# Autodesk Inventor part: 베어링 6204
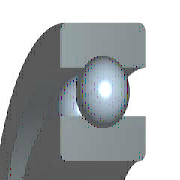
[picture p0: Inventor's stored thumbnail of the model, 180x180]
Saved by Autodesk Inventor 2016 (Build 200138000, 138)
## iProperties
IsCustomPart: 0
Created: 2018-09
Part Number: 베어링 6204
Material: 스테인리스강
Description: 깊은 그루브 볼 베어링
Document SubType Name: Modeling
Standard: KS B 2023
Standards Organization: KS
Language: ko-KR
Size Designation: 6204 - 20 x 47 x 14
Categories: <MemberInstance><Categories><Category DisplayName="샤프트 부품" InternalName="7f7aeb1f-a693-4053-b835-cee3144e0d98" Mnemonic="SHFT"><Category DisplayName="베어링" Inter
Density: 8.08 g/cm^3
Mass: 107.173 g
Surface Area: 87.8912 cm^2
Volume: 13.264 cm^3
Appearance: 노란색
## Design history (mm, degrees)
sketch "스케치" dims "d0" = 7.02 (= -0.26 x WD + 0.26 x BD)
  geometry: L1 (3.49, 16.75)-(10.51, 16.75); L2 (7, 16.75)-(7, 13.24); L3 (7, 16.75)-(7, 20.26); L4 (4.392, 14.401)-(0, 14.401); L5 (0, 10)-(14, 10); L6 (4.392, 19.099)-(0, 19.099); L7 (0, 23.5)-(14, 23.5); L8 (14, 10)-(14, 14.401); L9 (9.608, 14.401)-(14, 14.401); L10 (9.608, 19.099)-(14, 19.099); L11 (14, 23.5)-(14, 19.099); L12 (-1.4, 0)-(8.4, 0) reference; L13 (0, -0.3)-(0, 5.3) reference
  constraints: 22 end point, 4 point on line, 2 collinear, 2 perpendicular, 2 symmetric about line, 1 midpoint, 1 parallel, 14 other
  dimensions: "d9" = 20 diameter of L5 L12 (= WD); "d11" = 47 diameter of L7 L12 (= BD); "d12" = 14 distance between parallel lines of L8 L13 (= KB); "d13" = 28.802 diameter of L9 L12 (= 0.326 x BD + 0.674 x WD)
revolve "본체" stored, may be unused: angle "d6" = 90 deg
revolve "볼" stored, may be unused: angle "d7" = 90 deg
pattern_circular "IDS_ARRAYBALL[SIMPL:T]" dims angle "d3" = 360 deg
body "Solid1"
fillet "모깎기1" dims "d1" = 1 (= KRS)
other parameters: "WD" = 20 [user parameter; used in 5 equation terms], "BD" = 47 [user parameter; used in 5 equation terms], "KB" = 14 [user parameter; used in 1 equation term], "KRS" = 1 [user parameter; used in 1 equation term], "d4" = 0, "d5" = 0, "d8" = 0, "d14" = 0, "d15" = 0, "BBA" = 0 [user parameter], "BC0" = 6550000 [user parameter], "BC" = 1.27e+07 [user parameter], "BR" = 23.5 (= 0.5 x BD) [user parameter]
